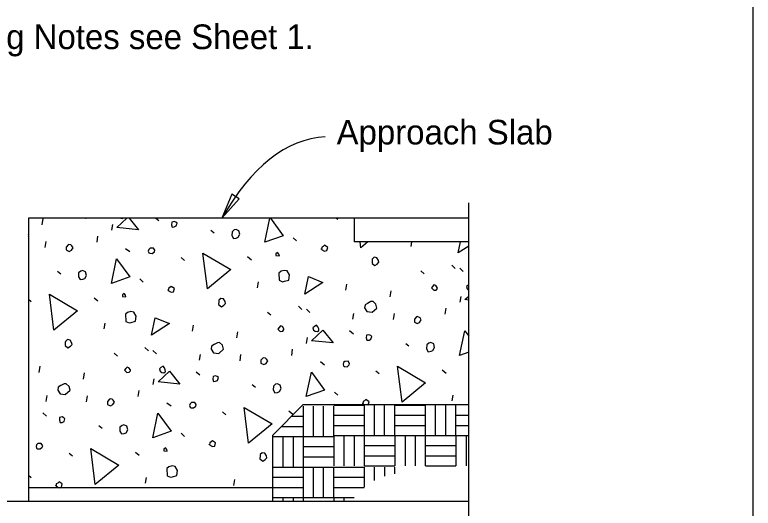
# Model space of a CAD drawing. Extents: x 112544 to 112597.1, y 111084 to 111107.1.
# Drawn here: x 112570.246 to 112574.78, y 111092.66 to 111095.687 of the extents above; entities that cross this region are included whole.
import ezdxf

# ---------------------------------------------------------------- set-up
doc = ezdxf.new("R2010")
doc.units = 0
for name, color, linetype in [('ActivePts-ConstElements', 7, 'Continuous'), ('Dimension', 7, 'Continuous'), ('Lighting', 7, 'Continuous'), ('Miscellaneous', 7, 'Continuous'), ('SupstrConc', 7, 'Continuous'), ('TextStructures', 7, 'Continuous')]:
    doc.layers.add(name, color=color, linetype=linetype)

msp = doc.modelspace()

# ---------------------------------------------------------------- linework, layer by layer
at = {"layer": 'ActivePts-ConstElements'}
msp.add_lwpolyline([(112543.9918, 111085.9039), (112574.7797, 111085.9039), (112574.7797, 111105.3634), (112543.9918, 111105.3634)], close=True, dxfattribs=at)
at = {"layer": 'Dimension'}
msp.add_lwpolyline([(112571.5185, 111094.4391), (112571.6231, 111094.558), (112571.5781, 111094.5858)], close=True, dxfattribs=at)
msp.add_lwpolyline([(112573.0332, 111092.2463), (112573.0332, 111094.5328)], dxfattribs=at)
msp.add_ellipse((112572.2636, 111092.5703), major_axis=(0.1111, -2.3674), ratio=0.464296, start_param=3.141604, end_param=3.781059, dxfattribs=at)
at = {"layer": 'Lighting'}
msp.add_line((112573.0332, 111092.7019), (112569.9743, 111092.7019), dxfattribs=at)
at = {"layer": 'Miscellaneous'}
for p, q in [((112570.4146, 111094.3986), (112570.42, 111094.4363)), ((112570.8427, 111094.3658), (112570.8488, 111094.4011)), ((112571.1124, 111094.4392), (112571.1298, 111094.4246)), ((112572.2223, 111094.4392), (112572.2303, 111094.4322)), ((112573.0332, 111094.4392), (112572.3297, 111094.4392)), ((112571.4509, 111094.3657), (112571.4706, 111094.3503)), ((112570.7512, 111094.2921), (112570.7566, 111094.3298)), ((112571.9551, 111094.3196), (112571.976, 111094.2994)), ((112570.4339, 111094.2589), (112570.4394, 111094.2965)), ((112572.6788, 111094.2651), (112572.6837, 111094.2934)), ((112570.9271, 111094.2538), (112570.9528, 111094.2348)), ((112571.2682, 111094.1977), (112571.2885, 111094.1798)), ((112571.6756, 111094.2033), (112571.699, 111094.1837)), ((112572.9294, 111094.151), (112572.9503, 111094.1308)), ((112572.9782, 111094.1331), (112572.9992, 111094.1128)), ((112570.5092, 111094.1134), (112570.5288, 111094.0979)), ((112572.7396, 111094.1157), (112572.7599, 111094.0979)), ((112571.0133, 111094.0673), (112571.0342, 111094.047)), ((112571.737, 111094.0127), (112571.7431, 111094.048)), ((112572.2794, 111093.9976), (112572.2849, 111094.0353)), ((112572.5518, 111093.9567), (112572.5572, 111093.9944)), ((112570.7338, 111093.951), (112570.7572, 111093.9314)), ((112572.9799, 111093.9239), (112572.986, 111093.9592)), ((112570.3297, 111093.9425), (112570.3467, 111093.9275)), ((112571.7978, 111093.8634), (112571.8181, 111093.8455)), ((112571.9876, 111093.8987), (112572.0086, 111093.8784)), ((112572.0364, 111093.8807), (112572.0574, 111093.8605)), ((112572.8884, 111093.8502), (112572.8938, 111093.8879)), ((112572.3219, 111093.82), (112572.3279, 111093.8553)), ((112572.5711, 111093.8169), (112572.5766, 111093.8546)), ((112570.7953, 111093.7604), (112570.8013, 111093.7957)), ((112571.3377, 111093.7453), (112571.3431, 111093.7829)), ((112571.61, 111093.7044), (112571.6155, 111093.742)), ((112572.3018, 111093.75), (112572.3252, 111093.7303)), ((112572.0381, 111093.6715), (112572.0442, 111093.7068)), ((112571.0458, 111093.6464), (112571.0668, 111093.6261)), ((112571.9466, 111093.5978), (112571.952, 111093.6355)), ((112572.6464, 111093.6715), (112572.666, 111093.656)), ((112570.856, 111093.611), (112570.8763, 111093.5932)), ((112571.0946, 111093.6284), (112571.1156, 111093.6081)), ((112571.3801, 111093.5677), (112571.3862, 111093.603)), ((112571.6294, 111093.5646), (112571.6348, 111093.6023)), ((112572.1225, 111093.5596), (112572.1483, 111093.5406)), ((112570.3959, 111093.4929), (112570.4013, 111093.5306)), ((112571.36, 111093.4976), (112571.3834, 111093.478)), ((112572.4636, 111093.5034), (112572.4839, 111093.4856)), ((112572.871, 111093.5091), (112572.8944, 111093.4895)), ((112570.6683, 111093.452), (112570.6737, 111093.4897)), ((112571.0963, 111093.4192), (112571.1024, 111093.4545)), ((112571.7046, 111093.4191), (112571.7243, 111093.4037)), ((112571.0048, 111093.3455), (112571.0102, 111093.3832)), ((112572.2087, 111093.373), (112572.2297, 111093.3527)), ((112570.4383, 111093.3153), (112570.4444, 111093.3506)), ((112570.6876, 111093.3123), (112570.693, 111093.3499)), ((112572.9325, 111093.3185), (112572.9385, 111093.3538)), ((112571.1807, 111093.3072), (112571.2065, 111093.2882)), ((112572.0185, 111092.913), (112572.0185, 111093.2867)), ((112572.0797, 111093.1005), (112572.0797, 111093.2867)), ((112572.1422, 111093.1005), (112572.1422, 111093.2867)), ((112572.2046, 111093.2933), (112572.3933, 111093.2933)), ((112572.2047, 111093.1005), (112572.2047, 111093.2867)), ((112572.3933, 111092.9196), (112572.3933, 111093.2933)), ((112572.4546, 111093.1071), (112572.4546, 111093.2933)), ((112572.5171, 111093.1071), (112572.5171, 111093.2933)), ((112572.5796, 111093.2933), (112572.7683, 111093.2933)), ((112572.5796, 111093.1071), (112572.5796, 111093.2933)), ((112572.7683, 111092.9196), (112572.7683, 111093.2933)), ((112572.8296, 111093.1071), (112572.8296, 111093.2933)), ((112572.8921, 111093.1071), (112572.8921, 111093.2933)), ((112572.9546, 111093.1071), (112572.9546, 111093.2933)), ((112570.4183, 111093.2453), (112570.4416, 111093.2256)), ((112571.5218, 111093.2511), (112571.5422, 111093.2332)), ((112571.9293, 111093.2567), (112571.9526, 111093.2371)), ((112571.9453, 111093.2243), (112572.0185, 111093.2243)), ((112572.2046, 111093.2308), (112572.3933, 111093.2308)), ((112572.5796, 111093.2308), (112572.7683, 111093.2308)), ((112572.9546, 111093.2309), (112573.0332, 111093.2309)), ((112570.7628, 111093.1668), (112570.7825, 111093.1513)), ((112571.8828, 111093.1618), (112572.0185, 111093.1618)), ((112572.2046, 111093.1683), (112572.3933, 111093.1683)), ((112572.5796, 111093.1683), (112572.7683, 111093.1683)), ((112572.9546, 111093.1684), (112573.0332, 111093.1684)), ((112571.2669, 111093.1207), (112571.2879, 111093.1004)), ((112571.8297, 111093.1005), (112572.2047, 111093.1005)), ((112571.8922, 111093.1005), (112571.8922, 111092.913)), ((112571.9547, 111093.1005), (112571.9547, 111092.913)), ((112572.2046, 111093.1071), (112572.5796, 111093.1071)), ((112572.2046, 111093.1071), (112572.2046, 111092.9196)), ((112572.2671, 111093.1071), (112572.2671, 111092.9196)), ((112572.3296, 111093.1071), (112572.3296, 111092.9196)), ((112572.5796, 111093.1071), (112572.9546, 111093.1071)), ((112572.5796, 111093.1071), (112572.5796, 111092.9196)), ((112572.6421, 111093.1071), (112572.6421, 111092.9196)), ((112572.7046, 111093.1071), (112572.7046, 111092.9196)), ((112572.9546, 111093.1071), (112573.0332, 111093.1071)), ((112572.9546, 111093.1071), (112572.9546, 111092.9196)), ((112573.0171, 111093.1071), (112573.0171, 111092.9196)), ((112572.3933, 111093.0446), (112572.5796, 111093.0446)), ((112572.7683, 111093.0446), (112572.9546, 111093.0446)), ((112570.5801, 111092.9987), (112570.6004, 111092.9809)), ((112570.9875, 111093.0044), (112571.0109, 111092.9848)), ((112572.0185, 111093.038), (112572.2047, 111093.038)), ((112572.0185, 111092.9755), (112572.2047, 111092.9755)), ((112572.3933, 111092.9821), (112572.5796, 111092.9821)), ((112572.7683, 111092.9821), (112572.9546, 111092.9821)), ((112571.8297, 111092.913), (112572.0185, 111092.913)), ((112572.0185, 111092.913), (112572.2047, 111092.913)), ((112572.0185, 111092.7019), (112572.0185, 111092.913)), ((112572.0797, 111092.7267), (112572.0797, 111092.913)), ((112572.1422, 111092.7267), (112572.1422, 111092.913)), ((112572.2047, 111092.913), (112572.3935, 111092.913)), ((112572.2047, 111092.7267), (112572.2047, 111092.913)), ((112572.3933, 111092.9196), (112572.5796, 111092.9196)), ((112572.3935, 111092.7901), (112572.3935, 111092.913)), ((112572.4547, 111092.8302), (112572.4547, 111092.913)), ((112572.5172, 111092.8568), (112572.5172, 111092.913)), ((112572.5797, 111092.8707), (112572.5797, 111092.913)), ((112572.7683, 111092.9196), (112572.9546, 111092.9196)), ((112570.3297, 111092.8639), (112570.3461, 111092.848)), ((112571.0489, 111092.8138), (112571.055, 111092.8491)), ((112571.5913, 111092.7987), (112571.5967, 111092.8363)), ((112571.8297, 111092.8505), (112572.0185, 111092.8505)), ((112572.2047, 111092.8505), (112572.3935, 111092.8505)), ((112571.8297, 111092.7852), (112570.3297, 111092.7852)), ((112571.8297, 111092.788), (112572.0185, 111092.788)), ((112572.2047, 111092.788), (112572.3908, 111092.788)), ((112571.8297, 111092.7267), (112572.2047, 111092.7267)), ((112571.8922, 111092.7267), (112571.8922, 111092.7019)), ((112571.9547, 111092.7267), (112571.9547, 111092.7019)), ((112572.2047, 111092.7268), (112572.3305, 111092.7268)), ((112572.2047, 111092.7267), (112572.2047, 111092.7019)), ((112572.2672, 111092.7268), (112572.2672, 111092.7019)), ((112572.3297, 111092.7268), (112572.3297, 111092.7258))]:
    msp.add_line(p, q, dxfattribs=at)
for points in [[(112570.6804, 111094.4392), (112570.6808, 111094.4389), (112570.6841, 111094.4392)], [(112570.8721, 111094.3814), (112570.9343, 111094.4392)], [(112570.9487, 111094.4392), (112571.0052, 111094.3679), (112570.8721, 111094.3814)], [(112570.8976, 111094.4392), (112570.9088, 111094.4379), (112570.9103, 111094.4392)], [(112571.209, 111094.3992), (112571.2129, 111094.3848), (112571.2256, 111094.3856), (112571.2371, 111094.3912), (112571.2428, 111094.4083), (112571.2361, 111094.4143), (112571.2245, 111094.4189), (112571.21, 111094.415), (112571.209, 111094.3992)], [(112571.7815, 111094.2912), (112571.8129, 111094.4392)], [(112571.8157, 111094.4392), (112571.8948, 111094.3319), (112571.7815, 111094.2912)], [(112571.5803, 111094.3564), (112571.5788, 111094.3327), (112571.5889, 111094.3147), (112571.6064, 111094.3168), (112571.6178, 111094.3224), (112571.6284, 111094.3408), (112571.6226, 111094.3625), (112571.6049, 111094.3707), (112571.5928, 111094.3675), (112571.5803, 111094.3564)], [(112570.3297, 111094.3278), (112570.3321, 111094.3299), (112570.3297, 111094.3388)], [(112570.5625, 111094.2622), (112570.5622, 111094.244), (112570.5799, 111094.2358), (112570.5937, 111094.2421), (112570.605, 111094.2581), (112570.5969, 111094.2689), (112570.5901, 111094.2748), (112570.5792, 111094.2771), (112570.5744, 111094.2758), (112570.5625, 111094.2622)], [(112572.1297, 111094.2474), (112572.1481, 111094.2368), (112572.1626, 111094.2406), (112572.1677, 111094.2601), (112572.1487, 111094.2731), (112572.1403, 111094.2657), (112572.1313, 111094.2607), (112572.1297, 111094.2474), (112572.1284, 111094.2522)], [(112572.3703, 111094.2575), (112572.3657, 111094.2934)], [(112572.4138, 111094.2934), (112572.3703, 111094.2575)], [(112572.9687, 111094.2263), (112572.9832, 111094.2934)], [(112573.0332, 111094.2678), (112572.9687, 111094.2263)], [(112571.0688, 111094.2271), (112571.0749, 111094.2236), (112571.0907, 111094.2226), (112571.1033, 111094.2337), (112571.1061, 111094.2423), (112571.0974, 111094.2555), (112571.0768, 111094.2551), (112571.0685, 111094.2477), (112571.0662, 111094.2367), (112571.0688, 111094.2271)], [(112571.4285, 111094.0051), (112571.4005, 111094.2254), (112571.5727, 111094.124), (112571.4285, 111094.0051)], [(112571.8495, 111094.2111), (112571.8708, 111094.209), (112571.8682, 111094.2187), (112571.8601, 111094.2295), (112571.8494, 111094.2214), (112571.8495, 111094.2111)], [(112570.8397, 111094.0389), (112570.8717, 111094.1898), (112570.953, 111094.0796), (112570.8397, 111094.0389)], [(112572.4401, 111094.1804), (112572.4398, 111094.1622), (112572.4564, 111094.1486), (112572.472, 111094.1579), (112572.4822, 111094.1684), (112572.4789, 111094.1805), (112572.4696, 111094.1961), (112572.4531, 111094.1994), (112572.4406, 111094.1883), (112572.4401, 111094.1804)], [(112570.6385, 111094.104), (112570.6371, 111094.0803), (112570.6471, 111094.0623), (112570.6646, 111094.0644), (112570.6761, 111094.0701), (112570.6867, 111094.0885), (112570.6808, 111094.1102), (112570.6631, 111094.1184), (112570.651, 111094.1151), (112570.6385, 111094.104)], [(112571.8684, 111094.1023), (112571.8697, 111094.0586), (112571.8905, 111094.0487), (112571.9026, 111094.0519), (112571.9291, 111094.059), (112571.9334, 111094.0912), (112571.9191, 111094.1159), (112571.9002, 111094.1186), (112571.8809, 111094.1134), (112571.8684, 111094.1023)], [(112572.027, 111093.974), (112572.05, 111094.0811), (112572.1374, 111094.0449), (112572.027, 111093.974)], [(112571.1879, 111093.995), (112571.2063, 111093.9844), (112571.2208, 111093.9883), (112571.2259, 111094.0078), (112571.2069, 111094.0208), (112571.1985, 111094.0134), (112571.1895, 111094.0084), (112571.1879, 111093.995), (112571.1866, 111093.9998)], [(112572.8038, 111094.0113), (112572.818, 111093.997), (112572.8331, 111093.9984), (112572.8408, 111094.0083), (112572.8395, 111094.0131), (112572.8308, 111094.0263), (112572.8192, 111094.0309), (112572.8115, 111094.0211), (112572.8038, 111094.0113)], [(112573.0332, 111094.0311), (112573.0273, 111094.0272), (112573.0189, 111094.0197), (112573.0228, 111094.0053)], [(112573.0228, 111094.0053), (112573.0326, 111093.9975), (112573.0332, 111093.9975)], [(112570.4867, 111093.7528), (112570.4588, 111093.973), (112570.6309, 111093.8716), (112570.4867, 111093.7528)], [(112570.9078, 111093.9588), (112570.929, 111093.9567), (112570.9264, 111093.9664), (112570.9184, 111093.9771), (112570.9076, 111093.9691), (112570.9078, 111093.9588)], [(112571.4983, 111093.9281), (112571.498, 111093.9099), (112571.5146, 111093.8962), (112571.5302, 111093.9056), (112571.5404, 111093.916), (112571.5371, 111093.9281), (112571.5278, 111093.9437), (112571.5114, 111093.9471), (112571.4988, 111093.936), (112571.4983, 111093.9281)], [(112573.0093, 111093.9395), (112573.0332, 111093.9617)], [(112572.3941, 111093.8886), (112572.4078, 111093.8664), (112572.44, 111093.862), (112572.4693, 111093.888), (112572.4628, 111093.9122), (112572.4456, 111093.9282), (112572.4328, 111093.9274), (112572.4124, 111093.9168), (112572.3968, 111093.9074), (112572.3941, 111093.8886)], [(112573.0332, 111093.9371), (112573.0093, 111093.9395)], [(112570.9266, 111093.8499), (112570.9279, 111093.8063), (112570.9487, 111093.7963), (112570.9608, 111093.7996), (112570.9873, 111093.8067), (112570.9916, 111093.8389), (112570.9773, 111093.8635), (112570.9584, 111093.8662), (112570.9391, 111093.8611), (112570.9266, 111093.8499)], [(112571.0852, 111093.7216), (112571.1083, 111093.8287), (112571.1956, 111093.7926), (112571.0852, 111093.7216)], [(112572.6997, 111093.8203), (112572.6994, 111093.8021), (112572.7171, 111093.7939), (112572.7309, 111093.8002), (112572.7422, 111093.8162), (112572.7341, 111093.827), (112572.7273, 111093.8329), (112572.7164, 111093.8352), (112572.7116, 111093.8339), (112572.6997, 111093.8203)], [(112571.862, 111093.7589), (112571.8762, 111093.7446), (112571.8913, 111093.7461), (112571.899, 111093.7559), (112571.8977, 111093.7607), (112571.889, 111093.7739), (112571.8774, 111093.7786), (112571.8697, 111093.7688), (112571.862, 111093.7589)], [(112572.081, 111093.7529), (112572.0909, 111093.7452), (112572.1042, 111093.7436), (112572.1126, 111093.751), (112572.1124, 111093.7613), (112572.1068, 111093.7727), (112572.0987, 111093.7835), (112572.0855, 111093.7748), (112572.0771, 111093.7674), (112572.081, 111093.7529)], [(112572.0676, 111093.6872), (112572.138, 111093.7527), (112572.2006, 111093.6737), (112572.0676, 111093.6872)], [(112572.4044, 111093.705), (112572.4083, 111093.6905), (112572.421, 111093.6913), (112572.4325, 111093.697), (112572.4383, 111093.714), (112572.4315, 111093.72), (112572.4199, 111093.7247), (112572.4054, 111093.7208), (112572.4044, 111093.705)], [(112572.9769, 111093.597), (112573.0089, 111093.7479), (112573.0332, 111093.715)], [(112570.5566, 111093.6757), (112570.5563, 111093.6575), (112570.5729, 111093.6439), (112570.5885, 111093.6532), (112570.5986, 111093.6637), (112570.5954, 111093.6758), (112570.586, 111093.6914), (112570.5696, 111093.6947), (112570.557, 111093.6836), (112570.5566, 111093.6757)], [(112571.4523, 111093.6362), (112571.466, 111093.614), (112571.4982, 111093.6097), (112571.5275, 111093.6357), (112571.521, 111093.6598), (112571.5038, 111093.6759), (112571.4911, 111093.6751), (112571.4706, 111093.6644), (112571.455, 111093.6551), (112571.4523, 111093.6362)], [(112572.7757, 111093.6621), (112572.7743, 111093.6384), (112572.7843, 111093.6204), (112572.8018, 111093.6225), (112572.8133, 111093.6282), (112572.8239, 111093.6465), (112572.818, 111093.6683), (112572.8003, 111093.6765), (112572.7882, 111093.6732), (112572.7757, 111093.6621)], [(112573.0332, 111093.6172), (112572.9769, 111093.597)], [(112571.7579, 111093.568), (112571.7576, 111093.5498), (112571.7753, 111093.5416), (112571.7891, 111093.5479), (112571.8004, 111093.5638), (112571.7923, 111093.5746), (112571.7856, 111093.5806), (112571.7746, 111093.5828), (112571.7698, 111093.5815), (112571.7579, 111093.568)], [(112572.2642, 111093.5328), (112572.2703, 111093.5293), (112572.2861, 111093.5283), (112572.2987, 111093.5395), (112572.3016, 111093.548), (112572.2929, 111093.5612), (112572.2722, 111093.5609), (112572.2639, 111093.5534), (112572.2616, 111093.5425), (112572.2642, 111093.5328)], [(112570.9202, 111093.5066), (112570.9344, 111093.4923), (112570.9495, 111093.4937), (112570.9573, 111093.5036), (112570.956, 111093.5084), (112570.9473, 111093.5216), (112570.9357, 111093.5262), (112570.9279, 111093.5164), (112570.9202, 111093.5066)], [(112571.1258, 111093.4348), (112571.1962, 111093.5003), (112571.2588, 111093.4213), (112571.1258, 111093.4348)], [(112571.1392, 111093.5006), (112571.1491, 111093.4928), (112571.1624, 111093.4913), (112571.1708, 111093.4987), (112571.1706, 111093.509), (112571.165, 111093.5204), (112571.1569, 111093.5312), (112571.1437, 111093.5225), (112571.1354, 111093.5151), (112571.1392, 111093.5006)], [(112572.0351, 111093.3446), (112572.0672, 111093.4956), (112572.1485, 111093.3853), (112572.0351, 111093.3446)], [(112572.6239, 111093.3109), (112572.596, 111093.5311), (112572.7681, 111093.4297), (112572.6239, 111093.3109)], [(112571.4627, 111093.4526), (112571.4665, 111093.4381), (112571.4793, 111093.439), (112571.4907, 111093.4446), (112571.4965, 111093.4617), (112571.4897, 111093.4676), (112571.4781, 111093.4723), (112571.4636, 111093.4684), (112571.4627, 111093.4526)], [(112570.5105, 111093.3839), (112570.5242, 111093.3617), (112570.5565, 111093.3573), (112570.5857, 111093.3833), (112570.5793, 111093.4075), (112570.562, 111093.4235), (112570.5493, 111093.4227), (112570.5288, 111093.4121), (112570.5132, 111093.4027), (112570.5105, 111093.3839)], [(112571.8339, 111093.4098), (112571.8325, 111093.3861), (112571.8425, 111093.3681), (112571.86, 111093.3702), (112571.8715, 111093.3758), (112571.8821, 111093.3942), (112571.8763, 111093.4159), (112571.8585, 111093.4241), (112571.8465, 111093.4209), (112571.8339, 111093.4098)], [(112570.8161, 111093.3156), (112570.8158, 111093.2974), (112570.8335, 111093.2892), (112570.8474, 111093.2955), (112570.8586, 111093.3115), (112570.8505, 111093.3223), (112570.8438, 111093.3282), (112570.8328, 111093.3305), (112570.828, 111093.3292), (112570.8161, 111093.3156)], [(112572.4138, 111093.2934), (112572.4162, 111093.294), (112572.4213, 111093.3135), (112572.4023, 111093.3265), (112572.394, 111093.3191), (112572.3849, 111093.3141), (112572.3833, 111093.3008), (112572.3821, 111093.3056)], [(112571.3224, 111093.2805), (112571.3286, 111093.2769), (112571.3444, 111093.276), (112571.3569, 111093.2871), (112571.3598, 111093.2957), (112571.3511, 111093.3089), (112571.3305, 111093.3085), (112571.3221, 111093.3011), (112571.3199, 111093.2901), (112571.3224, 111093.2805)], [(112571.6822, 111093.0585), (112571.6542, 111093.2788), (112571.8263, 111093.1774), (112571.6822, 111093.0585)], [(112572.3833, 111093.3008), (112572.3961, 111093.2934)], [(112571.0934, 111093.0923), (112571.1254, 111093.2432), (112571.2067, 111093.133), (112571.0934, 111093.0923)], [(112570.5209, 111093.2003), (112570.5248, 111093.1858), (112570.5375, 111093.1866), (112570.5489, 111093.1923), (112570.5547, 111093.2093), (112570.5479, 111093.2153), (112570.5363, 111093.22), (112570.5218, 111093.2161), (112570.5209, 111093.2003)], [(112570.8921, 111093.1574), (112570.8907, 111093.1337), (112570.9007, 111093.1157), (112570.9183, 111093.1178), (112570.9297, 111093.1235), (112570.9403, 111093.1419), (112570.9345, 111093.1636), (112570.9168, 111093.1718), (112570.9047, 111093.1685), (112570.8921, 111093.1574)], [(112570.3807, 111093.0281), (112570.3868, 111093.0246), (112570.4026, 111093.0236), (112570.4151, 111093.0348), (112570.418, 111093.0433), (112570.4093, 111093.0565), (112570.3887, 111093.0562), (112570.3803, 111093.0487), (112570.3781, 111093.0378), (112570.3807, 111093.0281)], [(112571.4416, 111093.0484), (112571.4599, 111093.0378), (112571.4744, 111093.0417), (112571.4796, 111093.0612), (112571.4605, 111093.0742), (112571.4522, 111093.0668), (112571.4432, 111093.0618), (112571.4416, 111093.0484), (112571.4403, 111093.0532)], [(112570.7404, 111092.8062), (112570.7124, 111093.0264), (112570.8845, 111092.925), (112570.7404, 111092.8062)], [(112571.1614, 111093.0122), (112571.1827, 111093.0101), (112571.1801, 111093.0197), (112571.172, 111093.0305), (112571.1612, 111093.0225), (112571.1614, 111093.0122)], [(112571.752, 111092.9815), (112571.7517, 111092.9633), (112571.7683, 111092.9496), (112571.7839, 111092.959), (112571.794, 111092.9694), (112571.7908, 111092.9815), (112571.7814, 111092.9971), (112571.765, 111093.0005), (112571.7524, 111092.9894), (112571.752, 111092.9815)], [(112571.1802, 111092.9033), (112571.1816, 111092.8597), (112571.2023, 111092.8497), (112571.2144, 111092.853), (112571.241, 111092.8601), (112571.2453, 111092.8923), (112571.2309, 111092.9169), (112571.2121, 111092.9196), (112571.1928, 111092.9144), (112571.1802, 111092.9033)], [(112570.4998, 111092.7961), (112570.5182, 111092.7854), (112570.5327, 111092.7893), (112570.5378, 111092.8088), (112570.5188, 111092.8218), (112570.5104, 111092.8144), (112570.5014, 111092.8094), (112570.4998, 111092.7961), (112570.4985, 111092.8009)]]:
    msp.add_lwpolyline(points, dxfattribs=at)
at = {"layer": 'SupstrConc'}
for p, q in [((112572.3297, 111094.4392), (112570.3297, 111094.4392)), ((112570.3297, 111094.4392), (112570.3297, 111093.0642)), ((112572.3297, 111094.4392), (112572.3297, 111094.2934)), ((112573.0332, 111094.2934), (112572.3297, 111094.2934)), ((112571.8297, 111093.1087), (112572.0144, 111093.2934)), ((112573.0332, 111093.2934), (112572.0144, 111093.2934)), ((112571.8297, 111092.7019), (112571.8297, 111093.1087)), ((112570.3297, 111093.0642), (112570.3297, 111092.7019))]:
    msp.add_line(p, q, dxfattribs=at)

# ---------------------------------------------------------------- texts
at = {"layer": 'Dimension'}
msp.add_text('1.  For Box Girder Maintenance Lighting Notes see Sheet 1.', height=0.1512, dxfattribs=at).set_placement((112566.7213, 111095.4761))
at = {"layer": 'TextStructures'}
msp.add_text('Approach Slab', height=0.1512, dxfattribs=at).set_placement((112572.2222, 111094.8911))

doc.saveas('drawing.dxf')
